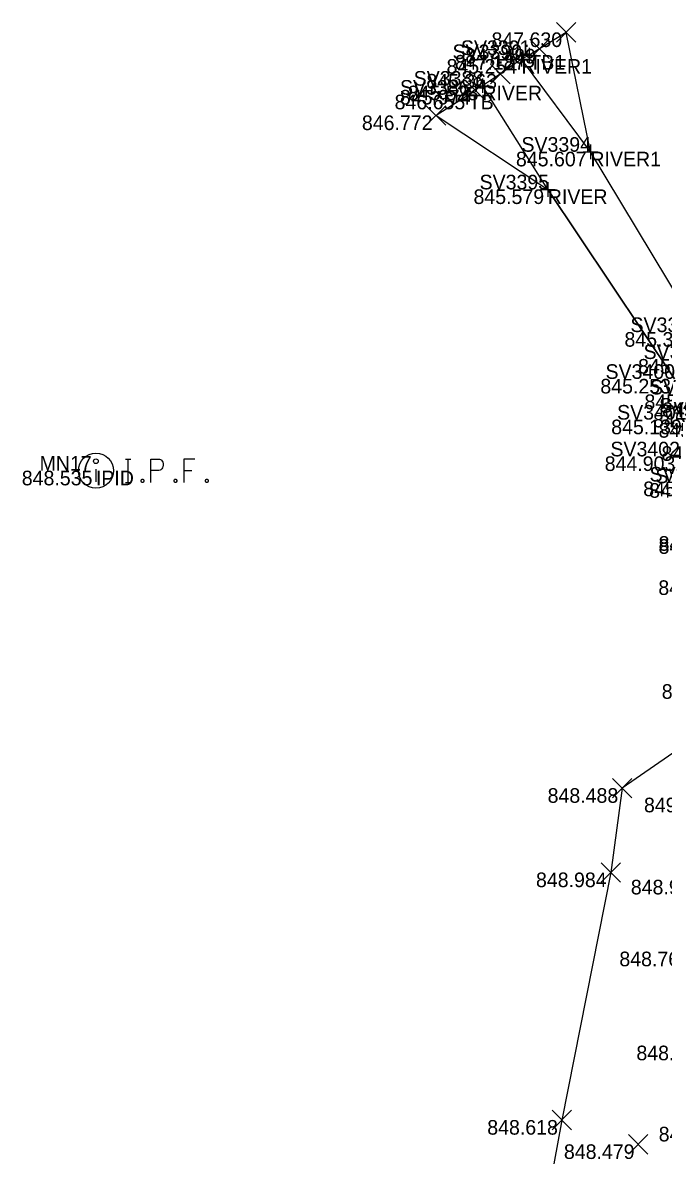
# Model space of a CAD drawing. Extents: x 2228183 to 2230895, y 679226 to 682223.
# Drawn here: x 2228182.5 to 2228226.4, y 680526.8 to 680604.3 of the extents above; entities that cross this region are included whole.
import ezdxf

# ---------------------------------------------------------------- set-up
doc = ezdxf.new("R2010")
doc.units = 0
for name, color, linetype in [('HY_X_Water_Edge', 7, 'Continuous'), ('RS_Raster1', 7, 'Continuous'), ('SC_Scratch1', 7, 'Continuous'), ('SV_P_Control_Cells_Set', 7, 'Continuous'), ('SV_X_Random_Point', 7, 'Continuous'), ('SV_X_Shot_Marker', 7, 'Continuous'), ('SV_X_Terrain_Boundary', 7, 'Continuous'), ('SV_X_Text_Comment', 7, 'Continuous')]:
    doc.layers.add(name, color=color, linetype=linetype)

msp = doc.modelspace()

# ---------------------------------------------------------------- linework, layer by layer
at = {"layer": 'HY_X_Water_Edge'}
for points in [[(2228228.816, 680583.157), (2228221.371, 680595.495), (2228216.649, 680601.835)], [(2228227.116, 680579.955), (2228218.454, 680592.92), (2228213.975, 680600.015)]]:
    msp.add_lwpolyline(points, dxfattribs=at)
at = {"layer": 'RS_Raster1'}
msp.add_line((2228187.526, 680573.789), (2228187.526, 680572.905), dxfattribs=at)
for points in [[(2228189.556, 680574.472), (2228189.909, 680574.472)], [(2228189.733, 680572.872), (2228189.733, 680574.472)], [(2228191.298, 680572.872), (2228191.298, 680574.472), (2228191.827, 680574.472), (2228191.882, 680574.459), (2228191.959, 680574.434), (2228191.993, 680574.409), (2228192.025, 680574.384), (2228192.07, 680574.321), (2228192.103, 680574.258), (2228192.125, 680574.157), (2228192.125, 680574.006), (2228192.114, 680573.955), (2228192.092, 680573.88), (2228192.048, 680573.792), (2228192.003, 680573.754), (2228191.97, 680573.729), (2228191.915, 680573.703), (2228191.827, 680573.691), (2228191.298, 680573.691)], [(2228194.307, 680574.472), (2228193.547, 680574.472), (2228193.547, 680572.872)], [(2228190.692, 680573.086), (2228190.747, 680573.086), (2228190.78, 680573.061), (2228190.813, 680573.011), (2228190.813, 680572.948), (2228190.78, 680572.897), (2228190.747, 680572.872), (2228190.692, 680572.872), (2228190.659, 680572.897), (2228190.626, 680572.948), (2228190.626, 680573.011), (2228190.659, 680573.061), (2228190.692, 680573.086)], [(2228192.94, 680573.086), (2228192.996, 680573.086), (2228193.029, 680573.061), (2228193.062, 680573.011), (2228193.062, 680572.948), (2228193.029, 680572.897), (2228192.996, 680572.872), (2228192.94, 680572.872), (2228192.907, 680572.897), (2228192.874, 680572.948), (2228192.874, 680573.011), (2228192.907, 680573.061), (2228192.94, 680573.086)], [(2228193.547, 680573.691), (2228194.087, 680573.691)], [(2228195.09, 680573.086), (2228195.145, 680573.086), (2228195.178, 680573.061), (2228195.211, 680573.011), (2228195.211, 680572.948), (2228195.178, 680572.897), (2228195.145, 680572.872), (2228195.09, 680572.872), (2228195.057, 680572.897), (2228195.024, 680572.948), (2228195.024, 680573.011), (2228195.057, 680573.061), (2228195.09, 680573.086)], [(2228189.556, 680572.872), (2228189.909, 680572.872)]]:
    msp.add_lwpolyline(points, dxfattribs=at)
for centre, radius in [((2228187.526, 680573.672), 1.2), ((2228187.526, 680574.324), 0.16)]:
    msp.add_circle(centre, radius, dxfattribs=at)
at = {"layer": 'SV_X_Random_Point'}
for p, q in [((2228219.05, 680602.992), (2228220.384, 680604.327)), ((2228219.05, 680604.327), (2228220.384, 680602.992)), ((2228217.223, 680601.864), (2228218.557, 680603.199)), ((2228217.223, 680603.199), (2228218.557, 680601.864)), ((2228214.542, 680600.149), (2228215.876, 680601.484)), ((2228214.542, 680601.484), (2228215.876, 680600.149)), ((2228212.788, 680599.059), (2228214.122, 680600.394)), ((2228212.788, 680600.394), (2228214.122, 680599.059)), ((2228210.137, 680597.31), (2228211.471, 680598.645)), ((2228210.137, 680598.645), (2228211.471, 680597.31)), ((2228222.875, 680551.284), (2228224.209, 680552.619)), ((2228222.875, 680552.619), (2228224.209, 680551.284)), ((2228222.101, 680545.514), (2228223.435, 680546.849)), ((2228222.101, 680546.849), (2228223.435, 680545.514)), ((2228218.744, 680528.58), (2228220.078, 680529.915)), ((2228218.744, 680529.915), (2228220.078, 680528.58)), ((2228223.974, 680526.917), (2228225.308, 680528.252)), ((2228223.974, 680528.252), (2228225.308, 680526.917))]:
    msp.add_line(p, q, dxfattribs=at)
at = {"layer": 'SV_X_Shot_Marker'}
for p, q in [((2228217.19, 680602.613), (2228217.19, 680601.613)), ((2228216.149, 680601.835), (2228217.149, 680601.835)), ((2228216.649, 680602.335), (2228216.649, 680601.335)), ((2228216.649, 680601.835), (2228216.649, 680601.835)), ((2228216.69, 680602.113), (2228217.69, 680602.113)), ((2228217.19, 680602.113), (2228217.19, 680602.113)), ((2228213.975, 680600.515), (2228213.975, 680599.515)), ((2228213.04, 680599.898), (2228213.04, 680598.898)), ((2228213.475, 680600.015), (2228214.475, 680600.015)), ((2228213.975, 680600.015), (2228213.975, 680600.015)), ((2228212.54, 680599.398), (2228213.54, 680599.398)), ((2228213.04, 680599.398), (2228213.04, 680599.398)), ((2228221.371, 680595.995), (2228221.371, 680594.995)), ((2228220.871, 680595.495), (2228221.871, 680595.495)), ((2228221.371, 680595.495), (2228221.371, 680595.495)), ((2228218.454, 680593.42), (2228218.454, 680592.42)), ((2228217.954, 680592.92), (2228218.954, 680592.92)), ((2228218.454, 680592.92), (2228218.454, 680592.92))]:
    msp.add_line(p, q, dxfattribs=at)
at = {"layer": 'SV_X_Terrain_Boundary'}
for points in [[(2228228.816, 680583.157), (2228221.371, 680595.495), (2228219.717, 680603.659), (2228217.89, 680602.531), (2228217.19, 680602.113), (2228216.649, 680601.835), (2228215.209, 680600.816), (2228213.975, 680600.015), (2228213.455, 680599.726), (2228213.04, 680599.398), (2228210.804, 680597.977), (2228218.454, 680592.92), (2228227.116, 680579.955)], [(2228231.428, 680557.402), (2228223.542, 680551.951), (2228222.768, 680546.181), (2228219.411, 680529.247), (2228217.574, 680519.169)]]:
    msp.add_lwpolyline(points, dxfattribs=at)

# ---------------------------------------------------------------- texts
at = {"layer": 'SC_Scratch1'}
for s, p in [('847.630', (2228214.603, 680602.659)), ('847.489', (2228212.806, 680601.531)), ('845.254', (2228211.527, 680600.835)), ('847.187', (2228212.094, 680601.113)), ('845.363', (2228210.145, 680599.816)), ('845.974', (2228208.333, 680598.726)), ('845.528', (2228208.875, 680599.015)), ('846.655', (2228207.97, 680598.398)), ('846.772', (2228205.731, 680596.977)), ('845.607', (2228216.275, 680594.495)), ('845.579', (2228213.37, 680591.92)), ('845.360', (2228223.702, 680582.157)), ('845.125', (2228224.633, 680580.314)), ('845.253', (2228222.052, 680578.955)), ('845.211', (2228225.071, 680577.889)), ('845.355', (2228226.278, 680577.345)), ('845.139', (2228222.794, 680576.167)), ('845.108', (2228225.655, 680576.639)), ('845.004', (2228226.031, 680575.933)), ('844.903', (2228222.348, 680573.654)), ('844.769', (2228226.237, 680574.349)), ('848.535', (2228182.456, 680572.672)), ('845.147', (2228224.985, 680571.93)), ('845.146', (2228225.395, 680571.819)), ('845.755', (2228226.036, 680568.195)), ('847.514', (2228226.034, 680567.987)), ('847.473', (2228226.019, 680565.172)), ('848.052', (2228226.251, 680558.066)), ('848.488', (2228218.442, 680550.951)), ('849.192', (2228225.036, 680550.301)), ('848.984', (2228217.646, 680545.181)), ('848.962', (2228224.138, 680544.684)), ('848.761', (2228223.352, 680539.768)), ('848.549', (2228224.519, 680533.336)), ('848.618', (2228214.311, 680528.247)), ('848.463', (2228226.044, 680527.784)), ('848.479', (2228219.557, 680526.584))]:
    msp.add_text(s, height=1, dxfattribs=at).set_placement(p)
at = {"layer": 'SV_P_Control_Cells_Set'}
for s, p in [('SV3390', (2228211.937, 680601.835)), ('SV3391', (2228212.51, 680602.113)), ('SV3388', (2228209.276, 680600.015)), ('SV3386', (2228208.338, 680599.398)), ('SV3394', (2228216.651, 680595.495)), ('SV3395', (2228213.785, 680592.92)), ('SV3396', (2228224.114, 680583.157)), ('SV3397', (2228225.009, 680581.314)), ('SV3400', (2228222.404, 680579.955)), ('SV3398', (2228225.454, 680578.889)), ('SV3399', (2228226.073, 680577.639)), ('SV3401', (2228223.198, 680577.167)), ('SV3402', (2228222.741, 680574.654)), ('MN17', (2228183.672, 680573.672)), ('SV3403', (2228225.419, 680572.93)), ('SV3281', (2228225.819, 680572.819))]:
    msp.add_text(s, height=1, dxfattribs=at).set_placement(p)
at = {"layer": 'SV_X_Text_Comment'}
for s, p in [('RIVER1', (2228216.649, 680600.835)), ('TB1', (2228217.19, 680601.113)), ('RIVER', (2228213.975, 680599.015)), ('TB', (2228213.04, 680598.398)), ('RIVER1', (2228221.371, 680594.495)), ('RIVER', (2228218.454, 680591.92)), ('IPID', (2228187.526, 680572.672))]:
    msp.add_text(s, height=1, dxfattribs=at).set_placement(p)

doc.saveas('drawing.dxf')
